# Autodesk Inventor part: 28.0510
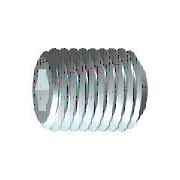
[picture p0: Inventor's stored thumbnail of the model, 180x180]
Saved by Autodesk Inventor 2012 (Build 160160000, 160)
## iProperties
IsCustomPart: 1
Created: 2006-02
Part Number: 28.0510
Material: Steel, Mild
Description: Hexagon Socket Set Screw
Document SubType Name: Modeling
Standard: DIN 913
Designer: Andy Moles
Standards Organization: DIN
Language: en-US
Size Designation: M6 x 25
Categories: <MemberInstance><Categories><Category DisplayName="Fasteners" InternalName="e4da775c-781d-43d5-af7c-5136215cf5a6" Mnemonic="FSTN"><Category DisplayName="Bolts"
Density: 7.86 g/cm^3
Mass: 5.26552 g
Surface Area: 5.51755 cm^2
Volume: 0.669913 cm^3
Stock Number: Timing Belt Pulley LR 6
Author: Andy Moles
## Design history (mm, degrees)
revolve "Body" stored, may be unused: angle "d6" = 90 deg
sketch "Sketch2"
  geometry: L1 (-0.866, 1.5)-(0.866, 1.5); L2 (0.866, 1.5)-(1.732, 0); L3 (1.732, 0)-(0.866, -1.5); L4 (0.866, -1.5)-(-0.866, -1.5); L5 (-0.866, -1.5)-(-1.732, 0); L6 (-1.732, 0)-(-0.866, 1.5); 3 further points
  constraints: 12 end point, 1 coincident, 1 horizontal, 13 other
extrude "Slot" join sketch "Sketch2" taper "d7" = 0 deg; stored distance "d21" = 10
workaxis "Work Axis1"
workplane "Work Plane1"
body "Solid1"
feature "Thread" dims "d8" = 25 (= NLG), "d9" = 0
chamfer "Chamfer1" distance "d10" = 0.61345 (= -0.5 x GD1 + 0.5 x NND); stored, may be unused: angle "d11" = 45 deg (= FAWI), second distance "d34" = 0.61345 (= -0.5 x GD1 + 0.5 x NND)
chamfer "Chamfer2" distance "d12" = 0.61345 (= -0.5 x GD1 + 0.5 x NND); stored, may be unused: angle "d13" = 45 deg (= FAWI), second distance "d35" = 0.61345 (= -0.5 x GD1 + 0.5 x NND)
sketch "Sketch1"
  geometry: L1 (0, 0)-(20.5, 0); L2 (25, 1.732)-(25, 3); L3 (25, 3)-(0, 3); L4 (25, 1.732)-(21.5, 1.732); L5 (21.5, 1.732)-(20.5, 0); L6 (0, -0.3)-(0, 3.9) reference; L7 (0, 3)-(0, 0)
  constraints: 13 end point, 3 parallel, 1 collinear, 1 perpendicular, 1 point on line
  dimensions: "d0" = 3.5 distance of L2.start L4.end (= INTI); "d1" = 60 deg angle of L5 L1; "d2" = 6 diameter of L3 L1 (= NND); "d3" = 3.4641 diameter of L4 L1 (= 1.1547 x SW); "d5" = 25 distance from line of L2 L3.end (= NLG)
other parameters: "NND" = 6 [user parameter; used in 5 equation terms], "NLG" = 25 [user parameter; used in 2 equation terms], "INTI" = 3.5 [user parameter; used in 1 equation term], "FAWI" = 45 deg [user parameter; used in 2 equation terms], "SW" = 3 [user parameter; used in 2 equation terms], "GD1" = 4.7731 (= THREADDIA - 1.2269 x PTC) [user parameter; used in 4 equation terms], "d4" = 0, "SPD" = 4 [user parameter], "d33" = 0, "d36" = 0, "GUL" = 0.61345 (= 0.61345 x PTC) [user parameter], "TOA" = 30 deg [user parameter], "THREADDIA" = 6 [user parameter; used in 1 equation term], "PTC" = 1 [user parameter; used in 4 equation terms], "FAWI1" = 45 deg [user parameter], "GAL" = 0.61345 (= 0.61345 x PTC) [user parameter], "E0" = 3.465 (= 1.155 x SW) [user parameter]
